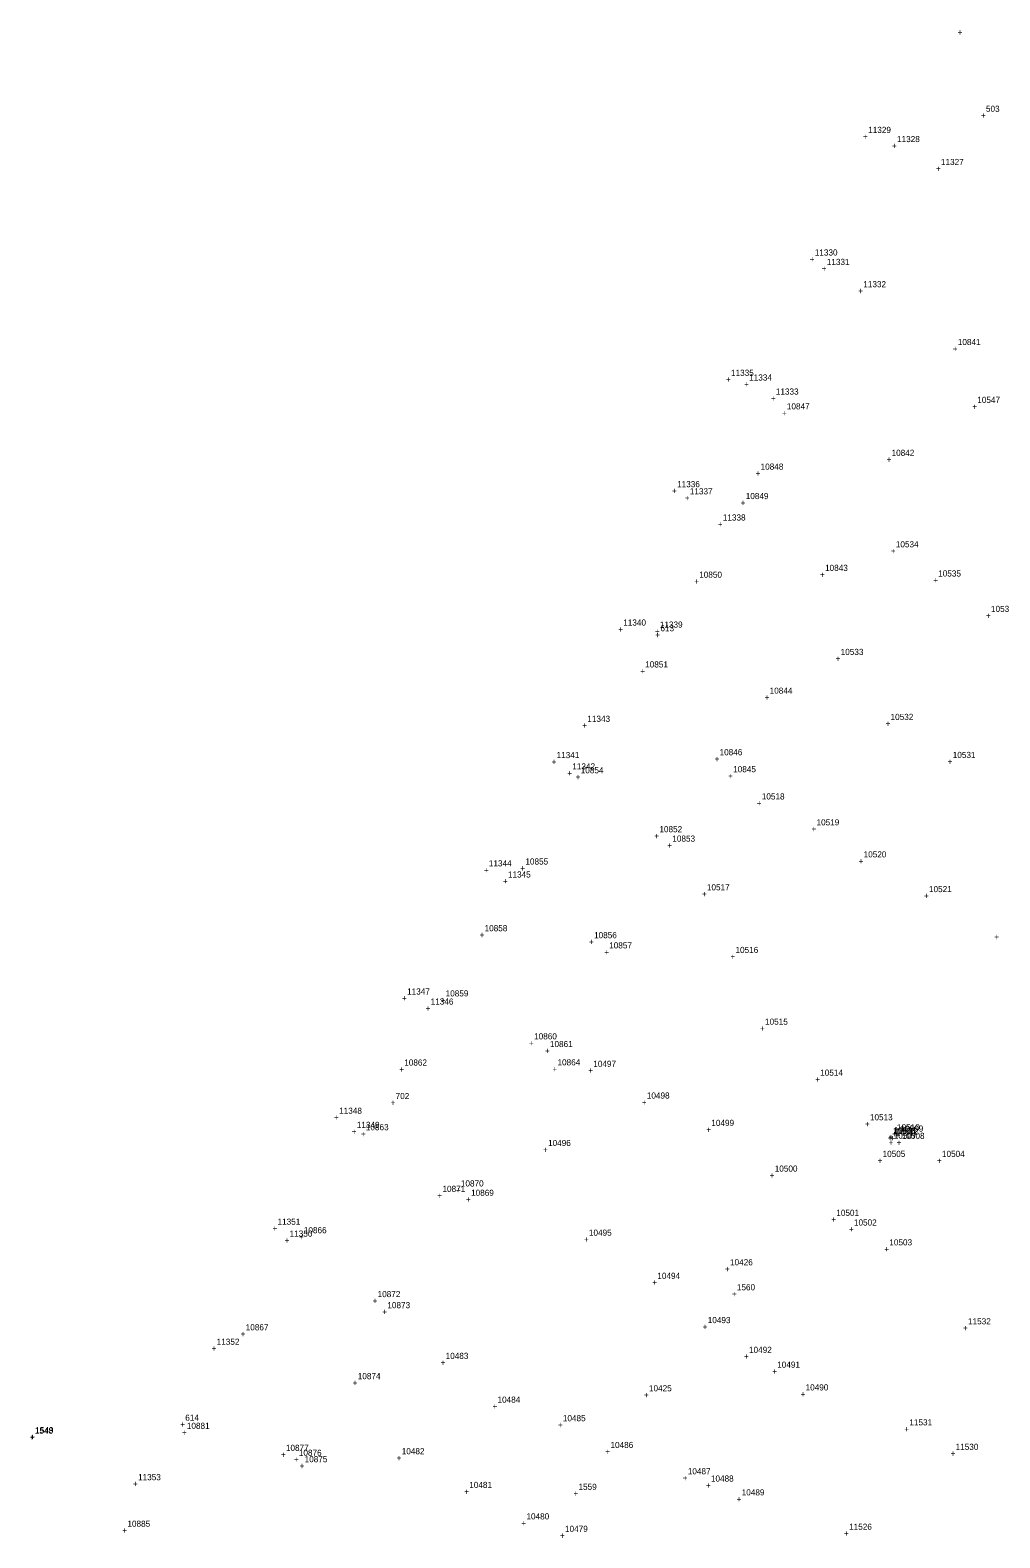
# Model space of a CAD drawing. Extents: x 1160051 to 1162814, y 614604 to 619560.
# Drawn here: x 1161385 to 1161781, y 617714 to 618329 of the extents above; entities that cross this region are included whole.
import ezdxf

# ---------------------------------------------------------------- set-up
doc = ezdxf.new("R2010")
doc.units = 0
for name, color, linetype in [('S_Control_Temp_Traverse', 7, 'Continuous'), ('S_Control_Traverse_Point', 7, 'Continuous'), ('S_Drainage_Culvert_Top', 7, 'Continuous'), ('S_Drainage_Invert', 7, 'Continuous'), ('S_Ground_Elevation', 7, 'Continuous'), ('S_Guardrail_Beam', 7, 'Continuous'), ('S_Traffic_Sign_SinglePost', 7, 'Continuous'), ('S_Trees_TreeLine', 7, 'Continuous'), ('S_Utilities_UG_BoringLocation', 7, 'Continuous')]:
    doc.layers.add(name, color=color, linetype=linetype)

msp = doc.modelspace()

# ---------------------------------------------------------------- texts
at = {"layer": 'S_Control_Temp_Traverse'}
for s, p in [('613', (1161642.03, 618083.56)), ('+', (1161639.97, 618080.81)), ('+', (1161446.01, 617758.64)), ('614', (1161448.08, 617761.39))]:
    msp.add_text(s, height=2.5, dxfattribs=at).set_placement(p)
at = {"layer": 'S_Control_Traverse_Point'}
for s, p in [('+', (1161772.85, 618292.78)), ('+', (1161772.85, 618292.78)), ('503', (1161774.91, 618295.53)), ('503', (1161774.91, 618295.53)), ('702', (1161533.95, 617892.67)), ('702', (1161533.95, 617892.67)), ('702', (1161533.95, 617892.67)), ('+', (1161531.88, 617889.92)), ('+', (1161531.88, 617889.92)), ('+', (1161531.88, 617889.92))]:
    msp.add_text(s, height=2.5, dxfattribs=at).set_placement(p)
at = {"layer": 'S_Drainage_Culvert_Top'}
for s, p in [('+', (1161735.9, 617875.45)), ('10512', (1161737.96, 617878.2)), ('+', (1161384.59, 617753.36)), ('1548', (1161386.66, 617756.11))]:
    msp.add_text(s, height=2.5, dxfattribs=at).set_placement(p)
at = {"layer": 'S_Drainage_Invert'}
for s, p in [('+', (1161735.23, 617875.97)), ('10511', (1161737.29, 617878.72)), ('+', (1161384.82, 617753.57)), ('1549', (1161386.88, 617756.32))]:
    msp.add_text(s, height=2.5, dxfattribs=at).set_placement(p)
at = {"layer": 'S_Ground_Elevation'}
for s, p in [('+', (1161763.36, 618326.76)), ('11329', (1161726.84, 618286.91)), ('+', (1161724.77, 618284.16)), ('+', (1161736.56, 618280.42)), ('11328', (1161738.62, 618283.17)), ('11327', (1161756.55, 618273.82)), ('+', (1161754.48, 618271.07)), ('11330', (1161705.05, 618236.89)), ('+', (1161702.99, 618234.14)), ('11331', (1161709.95, 618233.04)), ('+', (1161707.89, 618230.29)), ('+', (1161722.79, 618221.21)), ('11332', (1161724.85, 618223.96)), ('10841', (1161763.43, 618200.35)), ('+', (1161761.37, 618197.6)), ('11335', (1161670.85, 618187.79)), ('+', (1161668.79, 618185.04)), ('+', (1161676.2, 618183.13)), ('11334', (1161678.26, 618185.88)), ('+', (1161687.09, 618177.38)), ('11333', (1161689.15, 618180.13)), ('10547', (1161771.37, 618176.73)), ('+', (1161769.3, 618173.98)), ('+', (1161734.33, 618152.38)), ('10842', (1161736.39, 618155.13)), ('+', (1161646.79, 618139.61)), ('11336', (1161648.85, 618142.36)), ('11337', (1161654.04, 618139.43)), ('+', (1161651.98, 618136.68)), ('11338', (1161667.51, 618128.75)), ('+', (1161665.45, 618126.01)), ('+', (1161736.07, 618115.07)), ('10534', (1161738.13, 618117.82)), ('10843', (1161709.24, 618108.18)), ('+', (1161707.18, 618105.43)), ('+', (1161753.36, 618103.15)), ('10535', (1161755.42, 618105.9)), ('10536', (1161776.97, 618091.44)), ('11340', (1161626.85, 618085.88)), ('11339', (1161641.8, 618085.04)), ('+', (1161774.91, 618088.69)), ('+', (1161624.79, 618083.13)), ('+', (1161639.74, 618082.29)), ('+', (1161713.56, 618071.14)), ('10533', (1161715.62, 618073.89)), ('+', (1161684.57, 618055.32)), ('10844', (1161686.63, 618058.07)), ('10532', (1161735.97, 618047.37)), ('+', (1161733.91, 618044.62)), ('+', (1161597.59, 618029.05)), ('11341', (1161599.65, 618031.8)), ('+', (1161759.31, 618029.1)), ('10531', (1161761.37, 618031.85)), ('+', (1161604, 618024.44)), ('11342', (1161606.07, 618027.19)), ('+', (1161669.67, 618023.28)), ('10845', (1161671.73, 618026.03)), ('+', (1161681.36, 618012.17)), ('10518', (1161683.42, 618014.92)), ('10519', (1161705.76, 618004.36)), ('10853', (1161646.89, 617997.71)), ('+', (1161703.7, 618001.61)), ('+', (1161644.83, 617994.96)), ('10520', (1161725, 617991.28)), ('11344', (1161572.01, 617987.61)), ('+', (1161722.94, 617988.53)), ('+', (1161569.94, 617984.86)), ('+', (1161577.74, 617980.32)), ('11345', (1161579.8, 617983.07)), ('+', (1161658.94, 617975.1)), ('10517', (1161661, 617977.85)), ('+', (1161749.59, 617974.35)), ('10521', (1161751.65, 617977.1)), ('10857', (1161621.12, 617954.14)), ('+', (1161778.38, 617957.59)), ('+', (1161619.06, 617951.39)), ('+', (1161670.62, 617949.53)), ('10516', (1161672.68, 617952.28)), ('+', (1161536.57, 617932.58)), ('11347', (1161538.63, 617935.33)), ('11346', (1161548.26, 617931.22)), ('+', (1161546.2, 617928.47)), ('+', (1161682.68, 617920.26)), ('10515', (1161684.74, 617923.01)), ('10861', (1161596.93, 617913.88)), ('+', (1161594.87, 617911.13)), ('10497', (1161614.63, 617905.82)), ('+', (1161612.57, 617903.07)), ('+', (1161705.2, 617899.46)), ('10514', (1161707.26, 617902.21)), ('10498', (1161636.49, 617892.86)), ('11348', (1161510.89, 617886.66)), ('+', (1161634.43, 617890.11)), ('+', (1161508.83, 617883.91)), ('11349', (1161518.1, 617880.88)), ('10499', (1161662.81, 617881.71)), ('+', (1161725.48, 617881.26)), ('10513', (1161727.54, 617884.01)), ('+', (1161516.04, 617878.13)), ('+', (1161660.75, 617878.96)), ('+', (1161734.82, 617875.62)), ('+', (1161736.56, 617877.17)), ('10506', (1161736.88, 617878.37)), ('10507', (1161737.28, 617876.48)), ('+', (1161737.98, 617876.62)), ('10510', (1161738.62, 617879.92)), ('10509', (1161740.04, 617879.37)), ('10508', (1161740.56, 617876.41)), ('+', (1161594.11, 617870.75)), ('10496', (1161596.17, 617873.5)), ('10505', (1161732.72, 617869.05)), ('+', (1161735.22, 617873.73)), ('+', (1161738.5, 617873.66)), ('10504', (1161756.97, 617869.05)), ('10500', (1161688.7, 617863.05)), ('+', (1161730.66, 617866.3)), ('+', (1161754.91, 617866.3)), ('10870', (1161560.58, 617856.99)), ('+', (1161686.64, 617860.3)), ('+', (1161558.51, 617854.24)), ('10501', (1161713.83, 617845.01)), ('+', (1161483.68, 617838.62)), ('11351', (1161485.74, 617841.37)), ('10495', (1161612.84, 617836.91)), ('+', (1161711.77, 617842.26)), ('+', (1161718.97, 617838.31)), ('10502', (1161721.03, 617841.06)), ('+', (1161488.61, 617833.77)), ('11350', (1161490.68, 617836.52)), ('+', (1161610.78, 617834.16)), ('10503', (1161735.48, 617832.95)), ('+', (1161733.42, 617830.2)), ('10494', (1161640.78, 617819.3)), ('+', (1161638.72, 617816.55)), ('10873', (1161530.57, 617807.33)), ('+', (1161528.51, 617804.58)), ('10493', (1161661.36, 617801.23)), ('11532', (1161767.6, 617800.73)), ('+', (1161659.3, 617798.48)), ('+', (1161765.54, 617797.98)), ('+', (1161458.84, 617789.64)), ('11352', (1161460.9, 617792.39)), ('10492', (1161678.2, 617789.11)), ('+', (1161552.3, 617783.87)), ('10483', (1161554.36, 617786.62)), ('+', (1161676.14, 617786.36)), ('10491', (1161689.71, 617783.05)), ('+', (1161687.65, 617780.3)), ('+', (1161699.23, 617771.01)), ('10490', (1161701.29, 617773.76)), ('+', (1161573.48, 617766.02)), ('10484', (1161575.54, 617768.77)), ('+', (1161600.15, 617758.46)), ('10485', (1161602.21, 617761.21)), ('11531', (1161743.65, 617759.5)), ('+', (1161741.59, 617756.75)), ('10876', (1161494.44, 617747.08)), ('10482', (1161536.45, 617747.73)), ('+', (1161619.59, 617747.52)), ('10486', (1161621.65, 617750.27)), ('+', (1161760.47, 617746.76)), ('11530', (1161762.53, 617749.51)), ('+', (1161492.38, 617744.33)), ('+', (1161534.39, 617744.98)), ('10487', (1161653.21, 617739.55)), ('+', (1161426.74, 617734.39)), ('11353', (1161428.81, 617737.14)), ('10481', (1161564, 617733.96)), ('+', (1161651.15, 617736.8)), ('+', (1161660.58, 617733.82)), ('10488', (1161662.64, 617736.57)), ('+', (1161561.94, 617731.21)), ('+', (1161673.16, 617728.18)), ('10489', (1161675.22, 617730.93)), ('10480', (1161587.35, 617721.13)), ('+', (1161585.29, 617718.38)), ('10479', (1161603.09, 617716.05)), ('11526', (1161719.06, 617716.9)), ('+', (1161601.02, 617713.3)), ('+', (1161717, 617714.15))]:
    msp.add_text(s, height=2.5, dxfattribs=at).set_placement(p)
at = {"layer": 'S_Guardrail_Beam'}
for s, p in [('+', (1161691.59, 618171.36)), ('10847', (1161693.65, 618174.11)), ('+', (1161680.87, 618146.75)), ('10848', (1161682.93, 618149.5)), ('+', (1161674.81, 618134.74)), ('10849', (1161676.87, 618137.49)), ('+', (1161655.81, 618102.66)), ('10850', (1161657.87, 618105.41)), ('+', (1161633.75, 618066.04)), ('10851', (1161635.81, 618068.79)), ('+', (1161664.12, 618030.21)), ('10846', (1161666.18, 618032.96)), ('+', (1161607.45, 618022.86)), ('10854', (1161609.51, 618025.61)), ('+', (1161639.56, 617998.8)), ('10852', (1161641.62, 618001.55)), ('+', (1161584.85, 617985.62)), ('10855', (1161586.92, 617988.37)), ('10858', (1161570.26, 617961.16)), ('+', (1161568.2, 617958.41)), ('+', (1161612.89, 617955.56)), ('10856', (1161614.95, 617958.31)), ('+', (1161552.3, 617931.8)), ('10859', (1161554.37, 617934.55)), ('10860', (1161590.48, 617917.02)), ('+', (1161588.42, 617914.27)), ('10862', (1161537.46, 617906.33)), ('+', (1161535.39, 617903.58)), ('+', (1161519.73, 617877.2)), ('10863', (1161521.79, 617879.95)), ('+', (1161551.01, 617852.02)), ('10871', (1161553.07, 617854.77)), ('10866', (1161496.48, 617837.91)), ('+', (1161494.42, 617835.16)), ('+', (1161524.53, 617809.09)), ('10872', (1161526.59, 617811.84)), ('+', (1161470.69, 617795.54)), ('10867', (1161472.75, 617798.29)), ('10881', (1161448.72, 617758.08)), ('+', (1161446.66, 617755.33)), ('+', (1161487.09, 617746.34)), ('10877', (1161489.15, 617749.09)), ('+', (1161422.4, 617715.38)), ('10885', (1161424.46, 617718.13))]:
    msp.add_text(s, height=2.5, dxfattribs=at).set_placement(p)
at = {"layer": 'S_Traffic_Sign_SinglePost'}
for s, p in [('11343', (1161612.2, 618046.6)), ('+', (1161610.14, 618043.85))]:
    msp.add_text(s, height=2.5, dxfattribs=at).set_placement(p)
at = {"layer": 'S_Trees_TreeLine'}
for s, p in [('10864', (1161600.02, 617906.41)), ('+', (1161597.96, 617903.66)), ('+', (1161562.68, 617850.44)), ('10869', (1161564.74, 617853.19)), ('10426', (1161670.45, 617824.82)), ('+', (1161668.39, 617822.07)), ('10874', (1161518.49, 617778.36)), ('+', (1161516.43, 617775.61)), ('+', (1161635.3, 617770.66)), ('10425', (1161637.36, 617773.41)), ('+', (1161494.74, 617741.73)), ('10875', (1161496.8, 617744.48))]:
    msp.add_text(s, height=2.5, dxfattribs=at).set_placement(p)
at = {"layer": 'S_Utilities_UG_BoringLocation'}
for s, p in [('1560', (1161673.24, 617814.62)), ('+', (1161671.18, 617811.87)), ('1559', (1161608.59, 617733.19)), ('+', (1161606.53, 617730.44))]:
    msp.add_text(s, height=2.5, dxfattribs=at).set_placement(p)

doc.saveas('drawing.dxf')
